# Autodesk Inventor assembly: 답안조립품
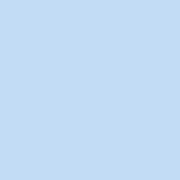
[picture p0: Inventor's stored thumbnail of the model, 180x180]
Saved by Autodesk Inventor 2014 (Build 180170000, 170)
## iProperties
Created: 2023-01
Part Number: 답안조립품
Document SubType Name: Assembly
Designer: dg
Author: dg
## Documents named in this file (1)
- C:\Users\dg\Desktop\730106V1023\답안조립품.iam
